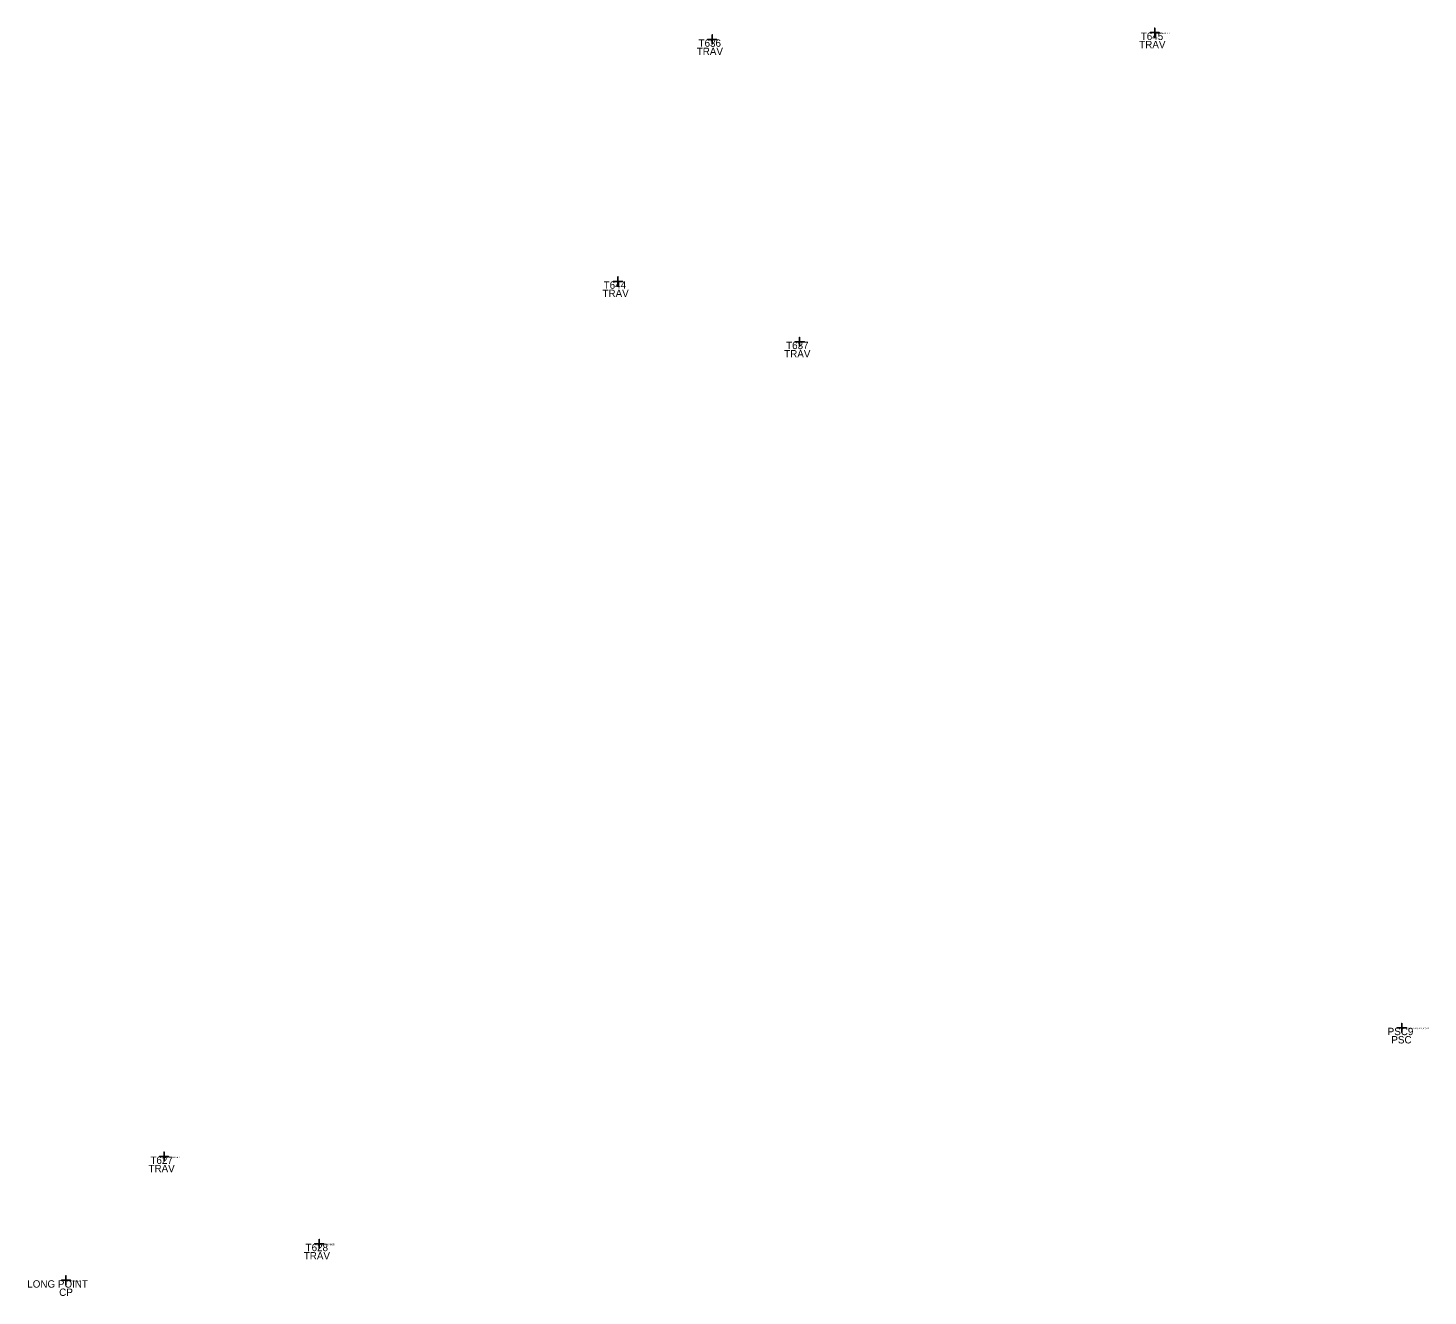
# Model space of a CAD drawing. Extents: x 2342247 to 2353588, y 365809 to 372747.
# Drawn here: x 2345725 to 2347246, y 367011 to 368389 of the extents above; entities that cross this region are included whole.
import ezdxf

# ---------------------------------------------------------------- set-up
doc = ezdxf.new("R2010")
doc.units = 0
for name, color, linetype in [('Level 63', 7, 'Continuous'), ('SV_Control_CP_Code', 7, 'Continuous'), ('SV_Control_CP_Name', 7, 'Continuous'), ('SV_Control_CP_Shot', 7, 'Continuous')]:
    doc.layers.add(name, color=color, linetype=linetype)

msp = doc.modelspace()

# ---------------------------------------------------------------- linework, layer by layer
at = {"layer": 'SV_Control_CP_Shot'}
for points in [[(2346468.6, 368376.1), (2346468.6, 368381.1), (2346468.6, 368376.1), (2346463.6, 368376.1), (2346468.6, 368376.1), (2346468.6, 368371.1), (2346468.6, 368376.1), (2346473.6, 368376.1)], [(2346949.3, 368383.5), (2346949.3, 368388.5), (2346949.3, 368383.5), (2346944.3, 368383.5), (2346949.3, 368383.5), (2346949.3, 368378.5), (2346949.3, 368383.5), (2346954.3, 368383.5)], [(2346366.2, 368113.2), (2346366.2, 368118.2), (2346366.2, 368113.2), (2346361.2, 368113.2), (2346366.2, 368113.2), (2346366.2, 368108.2), (2346366.2, 368113.2), (2346371.2, 368113.2)], [(2346563.6, 368047.6), (2346563.6, 368052.6), (2346563.6, 368047.6), (2346558.6, 368047.6), (2346563.6, 368047.6), (2346563.6, 368042.6), (2346563.6, 368047.6), (2346568.6, 368047.6)], [(2347217.7, 367302.3), (2347217.7, 367307.3), (2347217.7, 367302.3), (2347212.7, 367302.3), (2347217.7, 367302.3), (2347217.7, 367297.3), (2347217.7, 367302.3), (2347222.7, 367302.3)], [(2345873.1, 367162.4), (2345873.1, 367167.4), (2345873.1, 367162.4), (2345868.1, 367162.4), (2345873.1, 367162.4), (2345873.1, 367157.4), (2345873.1, 367162.4), (2345878.1, 367162.4)], [(2346041.7, 367067.6), (2346041.7, 367072.6), (2346041.7, 367067.6), (2346036.7, 367067.6), (2346041.7, 367067.6), (2346041.7, 367062.6), (2346041.7, 367067.6), (2346046.7, 367067.6)], [(2345766.6, 367028), (2345766.6, 367033), (2345766.6, 367028), (2345761.6, 367028), (2345766.6, 367028), (2345766.6, 367023), (2345766.6, 367028), (2345771.6, 367028)]]:
    msp.add_lwpolyline(points, close=True, dxfattribs=at)

# ---------------------------------------------------------------- texts
at = {"layer": 'Level 63'}
for s, p in [('NAIL W/WASHER', (2346949.3, 368382)), ('#5 REBAR W/ ALUMINUM CAP', (2347217.7, 367300.8)), ('NAIL W/WASHER', (2345873.1, 367160.9)), ('NAIL W/WASHER', (2346041.7, 367066.1)), ('NGS MONUMENT', (2345766.6, 367026.5))]:
    msp.add_text(s, height=1.5, dxfattribs=at).set_placement(p)
at = {"layer": 'SV_Control_CP_Code'}
for s, p in [('TRAV', (2346451.8, 368359.1)), ('TRAV', (2346932.5, 368366.5)), ('TRAV', (2346349.4, 368096.2)), ('TRAV', (2346546.8, 368030.6)), ('PSC', (2347206.4, 367285.3)), ('TRAV', (2345856.2, 367145.4)), ('TRAV', (2346024.9, 367050.6)), ('CP', (2345759.2, 367011))]:
    msp.add_text(s, height=8, dxfattribs=at).set_placement(p)
at = {"layer": 'SV_Control_CP_Name'}
for s, p in [('T645', (2346934.2, 368375.5)), ('T636', (2346453.8, 368368.1)), ('T644', (2346350.7, 368105.2)), ('T637', (2346548.9, 368039.6)), ('PSC9', (2347202.4, 367294.3)), ('T627', (2345858.3, 367154.4)), ('T628', (2346026.9, 367059.6)), ('LONG POINT', (2345724.5, 367020))]:
    msp.add_text(s, height=8, dxfattribs=at).set_placement(p)

doc.saveas('drawing.dxf')
